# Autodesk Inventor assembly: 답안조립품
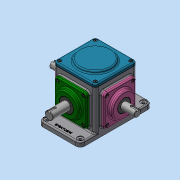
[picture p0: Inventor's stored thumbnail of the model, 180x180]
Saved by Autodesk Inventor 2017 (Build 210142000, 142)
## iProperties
Part Number: 답안조립품
Material: 일반
Document SubType Name: Assembly
Designer: MRC
Author: MRC
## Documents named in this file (16)
- C:\Users\MRC\Desktop\620307V1007\답안조립품.iam
- C:\Users\MRC\Desktop\620307V1007\본체.ipt
- C:\Users\MRC\Desktop\620307V1007\개스킷.ipt
- C:\Users\MRC\Desktop\620307V1007\메인베벨기어.ipt
- C:\Users\MRC\Desktop\620307V1007\메인축.ipt
- C:\Users\MRC\Desktop\620307V1007\메인커버.ipt
- C:\Users\MRC\Desktop\620307V1007\베어링 6203.ipt
- C:\Users\MRC\Desktop\620307V1007\베어링 6204.ipt
- C:\Users\MRC\Desktop\620307V1007\볼트 M4.ipt
- C:\Users\MRC\Desktop\620307V1007\상부커버.ipt
- C:\Users\MRC\Desktop\620307V1007\서브베벨기어.ipt
- C:\Users\MRC\Desktop\620307V1007\서브축.ipt
- C:\Users\MRC\Desktop\620307V1007\서브커버.ipt
- C:\Users\MRC\Desktop\620307V1007\오일 실 17 32 8.ipt
- C:\Users\MRC\Desktop\620307V1007\오일 실 20 35 8.ipt
- C:\Users\MRC\Desktop\620307V1007\키 4x4.ipt
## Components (1 placed, 1 different names)
1. 개스킷:1
